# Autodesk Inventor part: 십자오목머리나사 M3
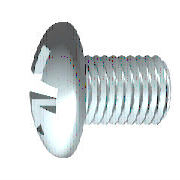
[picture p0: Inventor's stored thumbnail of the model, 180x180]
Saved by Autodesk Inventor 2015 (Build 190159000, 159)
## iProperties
Created: 2012-02
Part Number: 십자오목머리나사 M3
Material: 강철, 연강
Description: 십자 오목 머리 나사
Document SubType Name: Modeling
Standard: KS B 1023
Designer: mduedu
Standards Organization: KS
Language: ko-KR
Size Designation: A  M 3 x 6 - H
Categories: <MemberInstance><Categories><Category DisplayName="조임쇠" InternalName="e4da775c-781d-43d5-af7c-5136215cf5a6" Mnemonic="FSTN"><Category DisplayName="볼트" InternalN
Density: 7.86 g/cm^3
Appearance: 강철
Mass: 0.662382 g
Surface Area: 1.40192 cm^2
Volume: 0.0842726 cm^3
IsCustomPart: 0
Author: mduedu
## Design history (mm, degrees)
body "Solid1"
workplane "Work Plane3"
sketch "스케치2"
  geometry: L1 (-3.72, 0)-(3.72, 0) reference; L2 (0, -3.72)-(0, 3.72) reference; L3 (0, 1.5)-(0, 0); L4 (0, 0)-(1.5, 0); L5 (0, 0)-(1.879, 1.879); L6 (0.253, 1.479)-(0.261, 0.456); L7 (1.479, 0.253)-(0.456, 0.261); L8 (0.253, -1.479)-(0.261, -0.456); L9 (1.479, -0.253)-(0.456, -0.261); L10 (-0.253, 1.479)-(-0.261, 0.456); L11 (-1.479, 0.253)-(-0.456, 0.261); L12 (-1.479, -0.253)-(-0.456, -0.261); L13 (-0.253, -1.479)-(-0.261, -0.456); A1 r 0.45 centre (0, 0) between (0.45, 0) and (0, 0.45); A2 r 1.5 centre (0, 0) between (1.5, 0) and (1.479, 0.253); A3 r 1.5 centre (0, 0) between (0.253, 1.479) and (0, 1.5); A4 r 1.5 centre (0, 0) between (1.479, 0.253) and (0.253, 1.479); A5 r 1.5 centre (0, 0) between (0, -1.5) and (0.253, -1.479); A6 r 1.5 centre (0, 0) between (0.253, -1.479) and (1.479, -0.253); A7 r 1.5 centre (0, 0) between (1.479, -0.253) and (1.5, 0); A8 r 1.5 centre (0, 0) between (-1.479, 0.253) and (-1.5, 0); A9 r 1.5 centre (0, 0) between (-0.253, 1.479) and (-1.479, 0.253); A10 r 1.5 centre (0, 0) between (0, 1.5) and (-0.253, 1.479); A11 r 1.5 centre (0, 0) between (-1.5, 0) and (-1.479, -0.253); A12 r 1.5 centre (0, 0) between (-1.479, -0.253) and (-0.253, -1.479); A13 r 1.5 centre (0, 0) between (-0.253, -1.479) and (0, -1.5); A14 r 0.525 centre (0, 0) between (0.525, 0) and (0, 0.525); A15 r 0.197 centre (0.457, 0.457) between (0.261, 0.456) and (0.456, 0.261); A16 r 0.197 centre (0.457, -0.457) between (0.456, -0.261) and (0.261, -0.456); A17 r 0.197 centre (-0.457, 0.457) between (-0.456, 0.261) and (-0.261, 0.456); A18 r 0.197 centre (-0.457, -0.457) between (-0.261, -0.456) and (-0.456, -0.261); 1 further point
  constraints: 38 point on circle, 22 end point, 19 symmetric about line, 18 centre point, 4 coincident, 3 collinear, 3 point on line, 3 tangent, 1 perpendicular, 21 other
  dimensions: "d4" = 45 deg angle of L5 L4; "d5" = 0.9 diameter of A1 (= 0.3 x SDM); "d6" = 3 diameter of A4 (= SDM); "d7" = 0.2525 distance from line of L6.start L3 (= 0.5 x SBR); "d14" = 1.05 diameter of A14 (= 0.35 x SDM)
extrude "슬롯" join sketch "스케치2" taper "d15" = 5 deg; stored distance "d54" = 10
revolve "절단부" stored, may be unused: angle "d56" = 90 deg
revolve "본체" stored, may be unused: angle "d18" = 90 deg
workplane "Work Plane1"
sketch "스케치1"
  geometry: L1 (6, 0)-(6, 1.5); L2 (6, 1.5)-(1, 1.5); L3 (3.962, 5.08)-(3.962, 5.08); L4 (-2.4, 0)-(-2.4, 2.59); L5 (-2.2, 1.4)-(-1.036, 0.82); L6 (-1.036, 0.82)-(-0.6, 0); L7 (-0.6, 0)-(6, 0); L8 (-4.305, 0)-(7.717, 0) reference; L9 (0, -1.016)-(0, 6.096) reference; L10 (-2.2, 1.4)-(-2.4, 1.5); L11 (-1.636, 2.657)-(-2.4, 2.59); L12 (-1.636, 2.657)-(0, 2.8); L13 (0, 2.8)-(0, 1.347); L14 (0, 1.347)-(0.693, 1.347); L15 (0.693, 1.347)-(1, 1.5); L16 (1, 1.5)-(0, 1.5); A1 r 5 centre (2.6, 0) between (-1.636, 2.657) and (-2.4, 0)
  constraints: 28 end point, 5 point on line, 4 collinear, 4 point on circle, 3 parallel, 2 perpendicular, 1 centre point, 1 horizontal, 1 tangent
  dimensions: "d1" = 3 diameter of L2 L7 (= GD); "d2" = 1.8 distance from line of L6.end L4 (= STI); "d11" = 3 diameter of L10.end L7 (= SDM); "d12" = 62 deg angle of L6 L7; "d13" = 26.5 deg angle of L5 L7; "d17" = 5.6 diameter of L12.end L7 (= KOD); "d19" = 5 deg angle of L12 L7 (= KEWI); "d20" = 2.4 distance between parallel lines of L4 L13 (= KOH); "d21" = 5 radius of A1 (= KR); "d23" = 2.6935 diameter of L14 L7 (= BDM); "d24" = 5 distance of L1.end L2.end (= GEL); "d25" = 0.30673 horizontal distance of L14.end L2.end (= GAL); "d28" = 6 distance between parallel lines of L1 L13 (= NLG)
fillet "모깎기1" dims "d29" = 1.2 (= RR)
fillet "모깎기2" dims "d16" = 0.101 (= 0.2 x SBR)
feature "스레드" dims "d8" = 5 (= GEL), "d9" = 0
chamfer "모따기1" distance "d26" = 0.30673 (= -0.5 x SPD + 0.5 x GD); stored, may be unused: second distance "d27" = 0.30683 (computed from GUL), angle "d78" = 45 deg
other parameters: "GD" = 3 (= NND) [user parameter; used in 2 equation terms], "NLG" = 6 [user parameter; used in 1 equation term], "GEL" = 5 [user parameter; used in 2 equation terms], "KOD" = 5.6 [user parameter; used in 1 equation term], "KOH" = 2.4 [user parameter; used in 2 equation terms], "SDM" = 3 [user parameter; used in 4 equation terms], "STI" = 1.8 [user parameter; used in 1 equation term], "SBR" = 0.505 [user parameter; used in 2 equation terms], "GAL" = 0.30673 (= 0.61345 x PTC) [user parameter; used in 1 equation term], "SPD" = 2.38655 (= NND - 1.2269 x PTC) [user parameter; used in 1 equation term], "KEWI" = 5 deg [user parameter; used in 1 equation term], "d3" = -2.4 (= -KOH), "d10" = 0, "KR" = 5 [user parameter; used in 1 equation term], "BDM" = 2.6935 [user parameter; used in 1 equation term], "GUL" = 0.30673 (= 0.61345 x PTC) [user parameter; used in 1 equation term], "RR" = 1.2 [user parameter; used in 1 equation term], "d79" = 0, "d80" = 0, "PTC" = 0.5 [user parameter; used in 5 equation terms], "THREADDIA" = 3 [user parameter; used in 1 equation term], "TOA" = 30 deg [user parameter], "NND" = 3 [user parameter; used in 2 equation terms], "GD1" = 2.38655 (= THREADDIA - 1.2269 x PTC) [user parameter]
